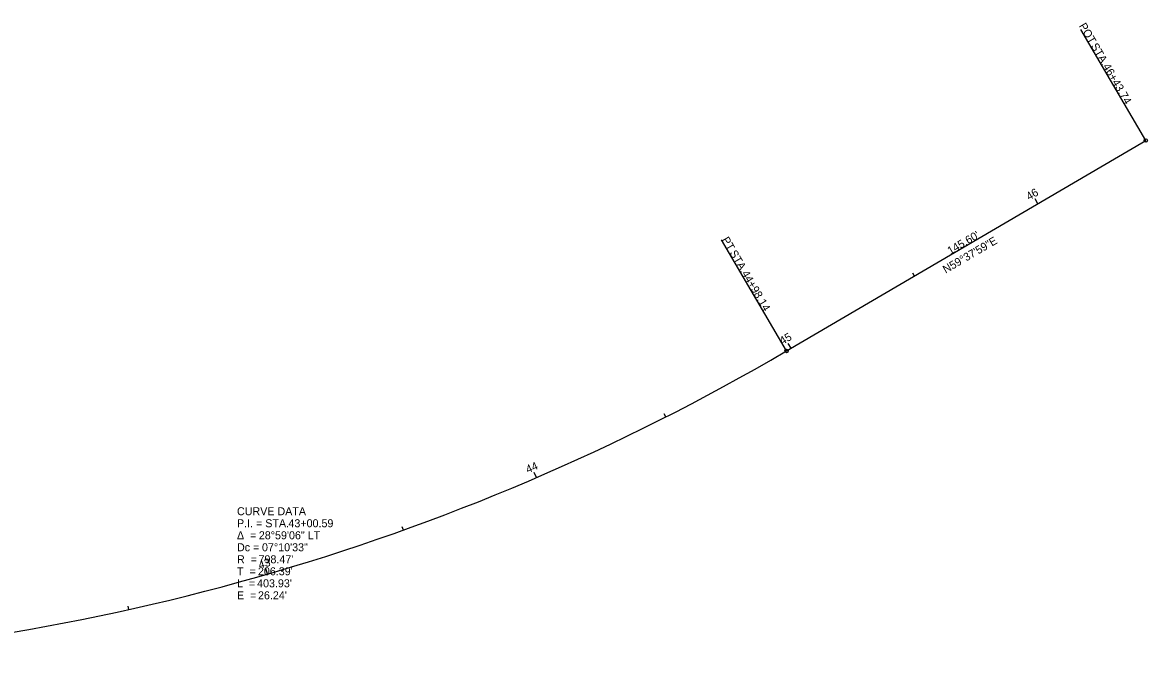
# Model space of a CAD drawing. Extents: x 1943743 to 1945350, y 152942 to 153188.
# Drawn here: x 1944956.5 to 1945350, y 152963.9 to 153188.1 of the extents above; entities that cross this region are included whole.
import ezdxf

# ---------------------------------------------------------------- set-up
doc = ezdxf.new("R2010")
doc.units = 0
for name, color, linetype in [('GE_X_Alignment', 7, 'Continuous'), ('GE_X_Alignment_100_Bearings', 7, 'Continuous'), ('GE_X_Alignment_100_Cardinal_Points', 7, 'Continuous'), ('GE_X_Alignment_100_Curve_Data', 7, 'Continuous'), ('GE_X_Alignment_100_Distances', 7, 'Continuous'), ('GE_X_Alignment_100_Stations', 7, 'Continuous')]:
    doc.layers.add(name, color=color, linetype=linetype)

msp = doc.modelspace()

# ---------------------------------------------------------------- linework, layer by layer
at = {"layer": 'GE_X_Alignment'}
msp.add_line((1945223.74, 153073.19), (1945349.36, 153146.79), dxfattribs=at)
msp.add_arc((1944820.08, 153762.11), 798.47, 271.38172, 300.36683, dxfattribs=at)
at = {"layer": 'GE_X_Alignment_100_Cardinal_Points'}
for p, q in [((1945349.36, 153146.79), (1945326.61, 153185.62)), ((1945223.74, 153073.19), (1945200.99, 153112.01))]:
    msp.add_line(p, q, dxfattribs=at)
for centre in [(1945349.36, 153146.79), (1945223.74, 153073.19)]:
    msp.add_circle(centre, 0.6, dxfattribs=at)
at = {"layer": 'GE_X_Alignment_100_Stations'}
for p, q in [((1945311.63, 153124.68), (1945310.62, 153126.41)), ((1945268.49, 153099.41), (1945267.88, 153100.44)), ((1945225.35, 153074.13), (1945224.34, 153075.86)), ((1945181.5, 153050.12), (1945180.96, 153051.19)), ((1945136.23, 153028.9), (1945135.44, 153030.73)), ((1945089.73, 153010.55), (1945089.33, 153011.68)), ((1945042.17, 152995.15), (1945041.61, 152997.07)), ((1944993.74, 152982.76), (1944993.48, 152983.93))]:
    msp.add_line(p, q, dxfattribs=at)

# ---------------------------------------------------------------- texts
at = {"layer": 'GE_X_Alignment_100_Bearings'}
msp.add_text('N59°37\'59"E', height=2.8, rotation=30.3669, dxfattribs=at).set_placement((1945279.38, 153100.23))
at = {"layer": 'GE_X_Alignment_100_Cardinal_Points'}
for s, p in [('POT', (1945325.89, 153186.93)), (' STA. ', (1945329.49, 153180.78)), ('46+43.74', (1945334.21, 153172.73)), ('PT', (1945200.97, 153112.12)), (' STA. ', (1945203.17, 153108.37)), ('44+98.14', (1945207.88, 153100.33))]:
    msp.add_text(s, height=2.8, rotation=300.3669, dxfattribs=at).set_placement(p)
at = {"layer": 'GE_X_Alignment_100_Curve_Data'}
for s, p in [('CURVE DATA', (1945031.54, 153015.73)), ('P.I. = STA. ', (1945031.54, 153011.53)), ('43+00.59', (1945049.53, 153011.53)), ('Δ  = ', (1945031.54, 153007.33)), ('28°59\'06" LT', (1945039.18, 153007.33)), ('Dc = ', (1945031.54, 153003.13)), ('07°10\'33"', (1945040.28, 153003.13)), ('R  = ', (1945031.54, 152998.93)), ("798.47'", (1945039.07, 152998.93)), ('T  = ', (1945031.54, 152994.73)), ("206.39'", (1945038.86, 152994.73)), ('L  = ', (1945031.54, 152990.53)), ("403.93'", (1945038.57, 152990.53)), ('E  = ', (1945031.54, 152986.33)), ("26.24'", (1945038.88, 152986.33))]:
    msp.add_text(s, height=2.8, dxfattribs=at).set_placement(p)
at = {"layer": 'GE_X_Alignment_100_Distances'}
msp.add_text("145.60'", height=2.8, rotation=30.3669, dxfattribs=at).set_placement((1945280.98, 153106.77))
at = {"layer": 'GE_X_Alignment_100_Stations'}
for s, rotation, p in [('46', 30.3669, (1945308.52, 153125.76)), ('45', 30.3669, (1945222.28, 153075.23)), ('44', 23.3249, (1945133.26, 153030.34)), ('43', 16.1492, (1945039.48, 152996.97))]:
    msp.add_text(s, height=2.8, rotation=rotation, dxfattribs=at).set_placement(p)

doc.saveas('drawing.dxf')
